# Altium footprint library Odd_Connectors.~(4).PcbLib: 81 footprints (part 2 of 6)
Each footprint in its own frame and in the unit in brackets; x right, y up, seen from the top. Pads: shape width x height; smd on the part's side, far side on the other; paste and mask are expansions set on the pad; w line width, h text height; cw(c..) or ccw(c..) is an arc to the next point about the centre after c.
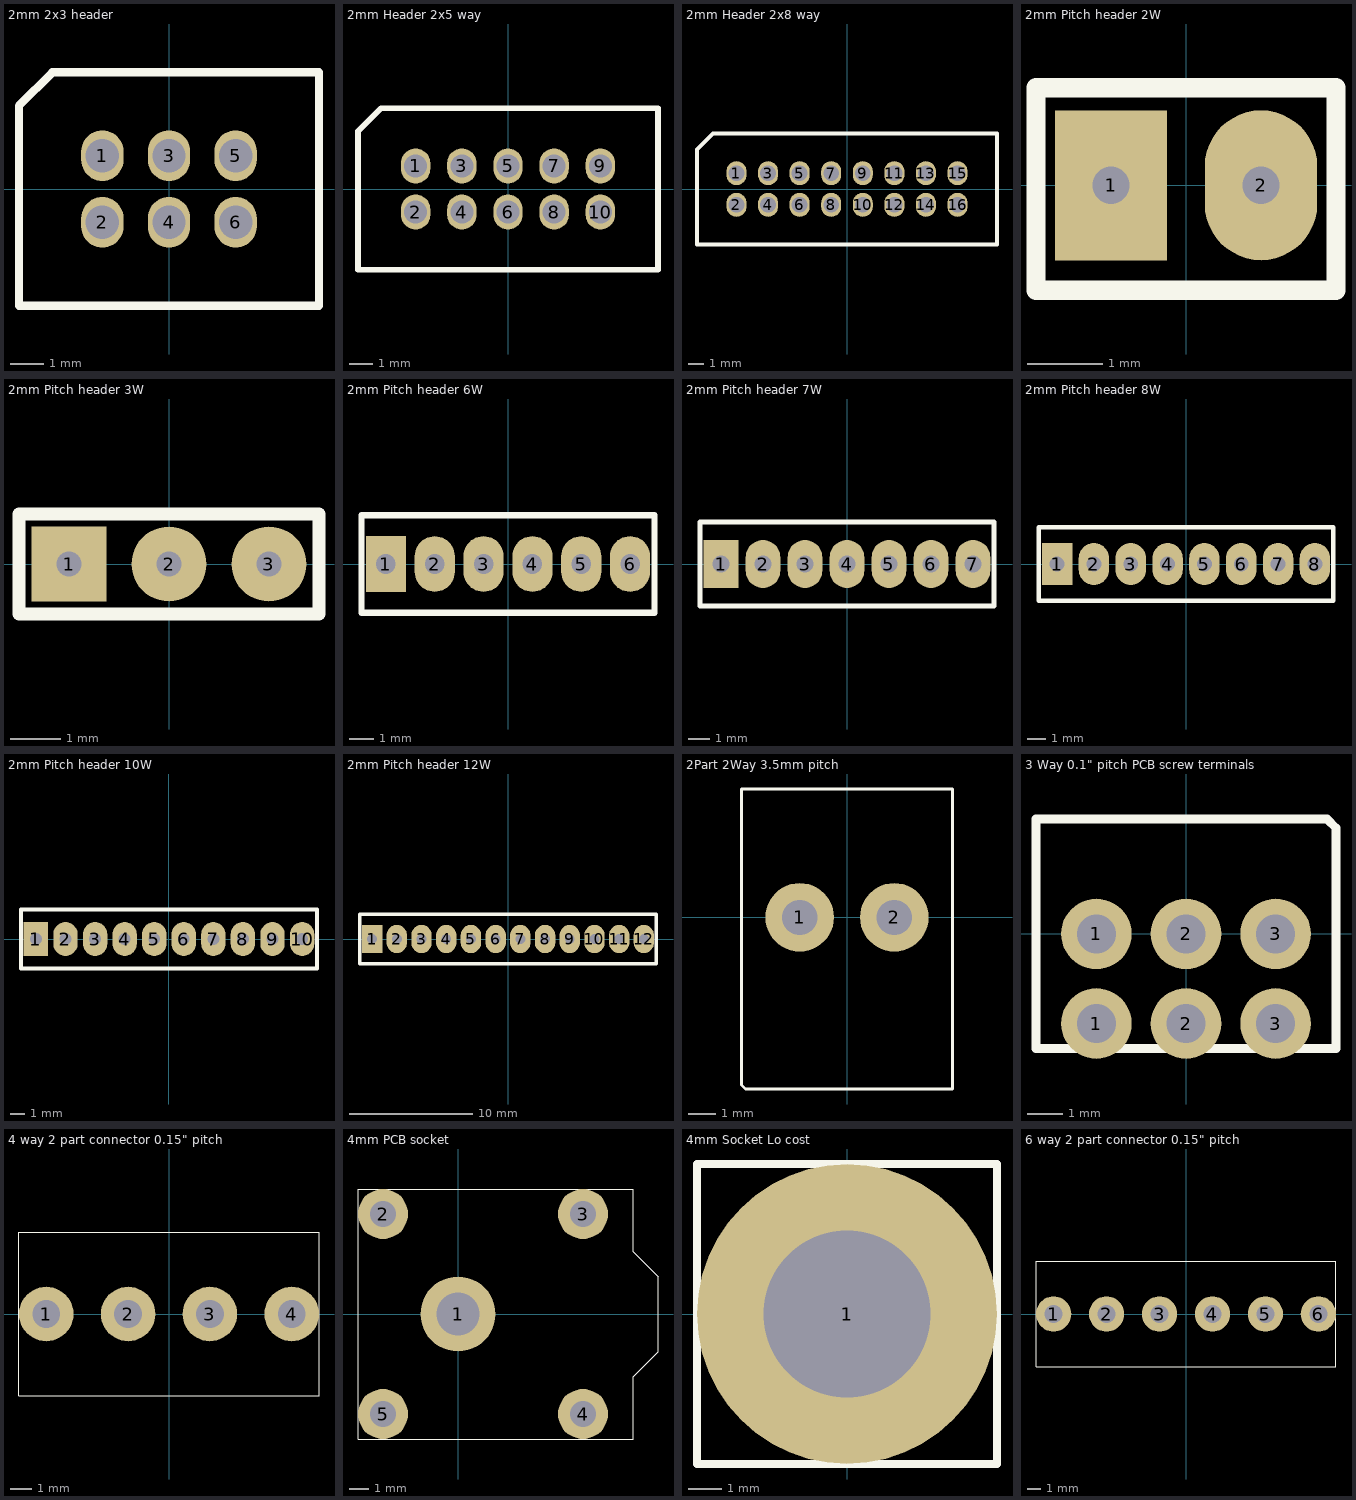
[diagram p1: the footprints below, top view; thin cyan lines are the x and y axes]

## 2mm 2x3 header [mm]
pads (6):
  oval 1.27x1.524 / inner round 1.524 / far side round 1.524 hole 1: 1(-2,1) 2(-2,-1) 3(0,1) 4(0,-1) 5(2,1) 6(2,-1)
Top Overlay:
  lines w0.254: -4.5,-3.5 4.5,-3.5 4.5,3.5 -3.5,3.5 -4.5,2.5 -4.5,-3.5

## 2mm Header 2x5 way [mm] "Milligrid 87831 etc"
pads (10):
  oval 1.27x1.524 / inner round 1.524 / far side round 1.524 hole 1: 1(-4,1) 2(-4,-1) 3(-2,1) 4(-2,-1) 5(0,1) 6(0,-1) 7(2,1) 8(2,-1) 9(4,1) 10(4,-1)
Top Overlay:
  lines w0.254: -6.5,-3.5 6.5,-3.5 6.5,3.5 -5.5,3.5 -6.5,2.5 -6.5,-3.5

## 2mm Header 2x8 way [mm] "Milligrid 87831 etc"
pads (16):
  oval 1.27x1.524 / inner round 1.524 / far side round 1.524 hole 1: 1(-7,1) 2(-7,-1) 3(-5,1) 4(-5,-1) 5(-3,1) 6(-3,-1) 7(-1,1) 8(-1,-1) 9(1,1) 10(1,-1) 11(3,1) 12(3,-1) 13(5,1) 14(5,-1) 15(7,1) 16(7,-1)
Top Overlay:
  lines w0.254: -9.5,-3.5 9.5,-3.5 9.5,3.5 -8.5,3.5 -9.5,2.5 -9.5,-3.5

## 2mm Pitch header 2W [mm] "2mm pitch single row 12W"
height 5
pads (2):
  rect 1.5x2 hole 0.5: 1(-1,0)
  oval 1.5x2 hole 0.5: 2(1,0)
Top Overlay:
  lines w0.254: -2,-1.4 2,-1.4 2,1.3 -2,1.3 -2,-1.4

## 2mm Pitch header 3W [mm] "2mm pitch single row 3W"
height 5
pads (3):
  rect 1.5x1.5 hole 0.5: 1(-2,0)
  round 1.5 hole 0.5: 2(0,0) 3(2,0)
Top Overlay:
  lines w0.254: -3,-1 -3,1 3,1 3,-1 -3,-1

## 2mm Pitch header 6W [mil] "2mm pitch single row 6W"
height 196.85
pads (6):
  rect 65x90 hole 31.5: 1(-196.85,0)
  oval 65x90 hole 31.5: 2(-118.11,0) 3(-39.37,0) 4(39.37,0) 5(118.11,0) 6(196.85,0)
Top Overlay:
  lines w10: -236.22,-78.74 236.22,-78.74 236.22,78.74 -236.22,78.74 -236.22,0 -236.22,-78.74

## 2mm Pitch header 7W [mil] "2mm pitch single row 7W"
height 196.85
pads (7):
  rect 65x90 hole 31.5: 1(-236.22,0)
  oval 65x90 hole 31.5: 2(-157.48,0) 3(-78.74,0) 4(0,0) 5(78.74,0) 6(157.48,0) 7(236.22,0)
Top Overlay:
  lines w10: -275.59,-78.74 275.59,-78.74 275.59,78.74 -275.59,78.74 -275.59,0 -275.59,-78.74

## 2mm Pitch header 8W [mil] "2mm pitch single row 8W"
height 196.85
pads (8):
  rect 65x90 hole 31.5: 1(-275.59,0)
  oval 65x90 hole 31.5: 2(-196.85,0) 3(-118.11,0) 4(-39.37,0) 5(39.37,0) 6(118.11,0) 7(196.85,0) 8(275.59,0)
Top Overlay:
  lines w10: -314.96,-78.74 314.96,-78.74 314.96,78.74 -314.96,78.74 -314.96,0 -314.96,-78.74

## 2mm Pitch header 10W [mil] "2mm pitch single row 10W"
height 196.85
pads (10):
  rect 65x90 hole 31.5: 1(-354.33,0)
  oval 65x90 hole 31.5: 2(-275.59,0) 3(-196.85,0) 4(-118.11,0) 5(-39.37,0) 6(39.37,0) 7(118.11,0) 8(196.85,0) 9(275.59,0) 10(354.33,0)
Top Overlay:
  lines w10: -393.7,-78.74 -393.7,0 -393.7,78.74 393.7,78.74 393.7,-78.74 -393.7,-78.74

## 2mm Pitch header 12W [mil] "2mm pitch single row 12W"
height 196.85
pads (12):
  rect 65x90 hole 31.5: 1(-433.07,0)
  oval 65x90 hole 31.5: 2(-354.33,0) 3(-275.59,0) 4(-196.85,0) 5(-118.11,0) 6(-39.37,0) 7(39.37,0) 8(118.11,0) 9(196.85,0) 10(275.59,0) 11(354.33,0) 12(433.07,0)
Top Overlay:
  lines w10: -472.44,-78.74 -472.44,0 -472.44,78.74 472.44,78.74 472.44,-78.74 -472.44,-78.74

## 2Part 2Way 3.5mm pitch [mm] "2Part 2Way 3.5mm pitch such as IMO 20.155/MV/02 + M/02"
height 15
pads (2):
  round 2.54 hole 1.3: 1(-1.75,0) 2(1.75,0)
Top Overlay:
  lines w0.1: -3.9,-6.2 -3.75,-6.35 3.9,-6.35 3.9,4.75 -3.9,4.75 -3.9,-6.2

## 3 Way 0.1" pitch PCB screw terminals [mm]
height 8.5
pads (6):
  round 2 hole 1.1: 1(-2.54,-2.54) 1(-2.54,0) 2(0,-2.54) 2(0,0) 3(2.54,-2.54) 3(2.54,0)
Top Overlay:
  lines w0.254: -4.25,-3.25 -4.25,3.25 4,3.25 4.25,3 4.25,-3.25 -4.25,-3.25

## 4 way 2 part connector 0.15" pitch [mm] "4 way connector or terminal block - 0.15\" pitch"
height 10.16
pads (4):
  round 2.54 hole 1.3 unplated: 1(-5.715,0) 2(-1.905,0) 3(1.905,0) 4(5.715,0)
Top Overlay:
  lines w0.025: -6.985,-3.81 -6.985,3.81 6.985,3.81 6.985,-3.81 -6.985,-3.81

## 4mm PCB socket [mm] "Gold plated PCB 4mm socket"
height 11.5
pads (5):
  round 3.81 hole 2.2 unplated: 1(0,0)
  round 2.54 hole 1.3 unplated: 2(-3.81,5.08) 3(6.35,5.08) 4(6.35,-5.08) 5(-3.81,-5.08)
Top Overlay:
  lines w0.025: -5.08,-6.35 8.89,-6.35 8.89,-3.175 10.16,-1.905 10.16,1.905 8.89,3.175 8.89,6.35 -5.08,6.35 -5.08,-6.35

## 4mm Socket Lo cost [mm] "Low cost 4mm socket"
pads (1):
  round 9 hole 5: 1(0,0)
Top Overlay:
  lines w0.254: -4.5,-4.5 4.5,-4.5 4.5,4.5 -4.5,4.5 -4.5,-4.5

## 6 way 2 part connector 0.15" pitch [mm] "6 way connector or terminal block - 0.15\" pitch"
height 10.16
pads (6):
  round 2.54 hole 1.3 unplated: 1(-9.525,0) 2(-5.715,0) 3(-1.905,0) 4(1.905,0) 5(5.715,0) 6(9.525,0)
Top Overlay:
  lines w0.025: -10.795,-3.81 -10.795,3.81 10.795,3.81 10.795,-3.81 -10.795,-3.81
